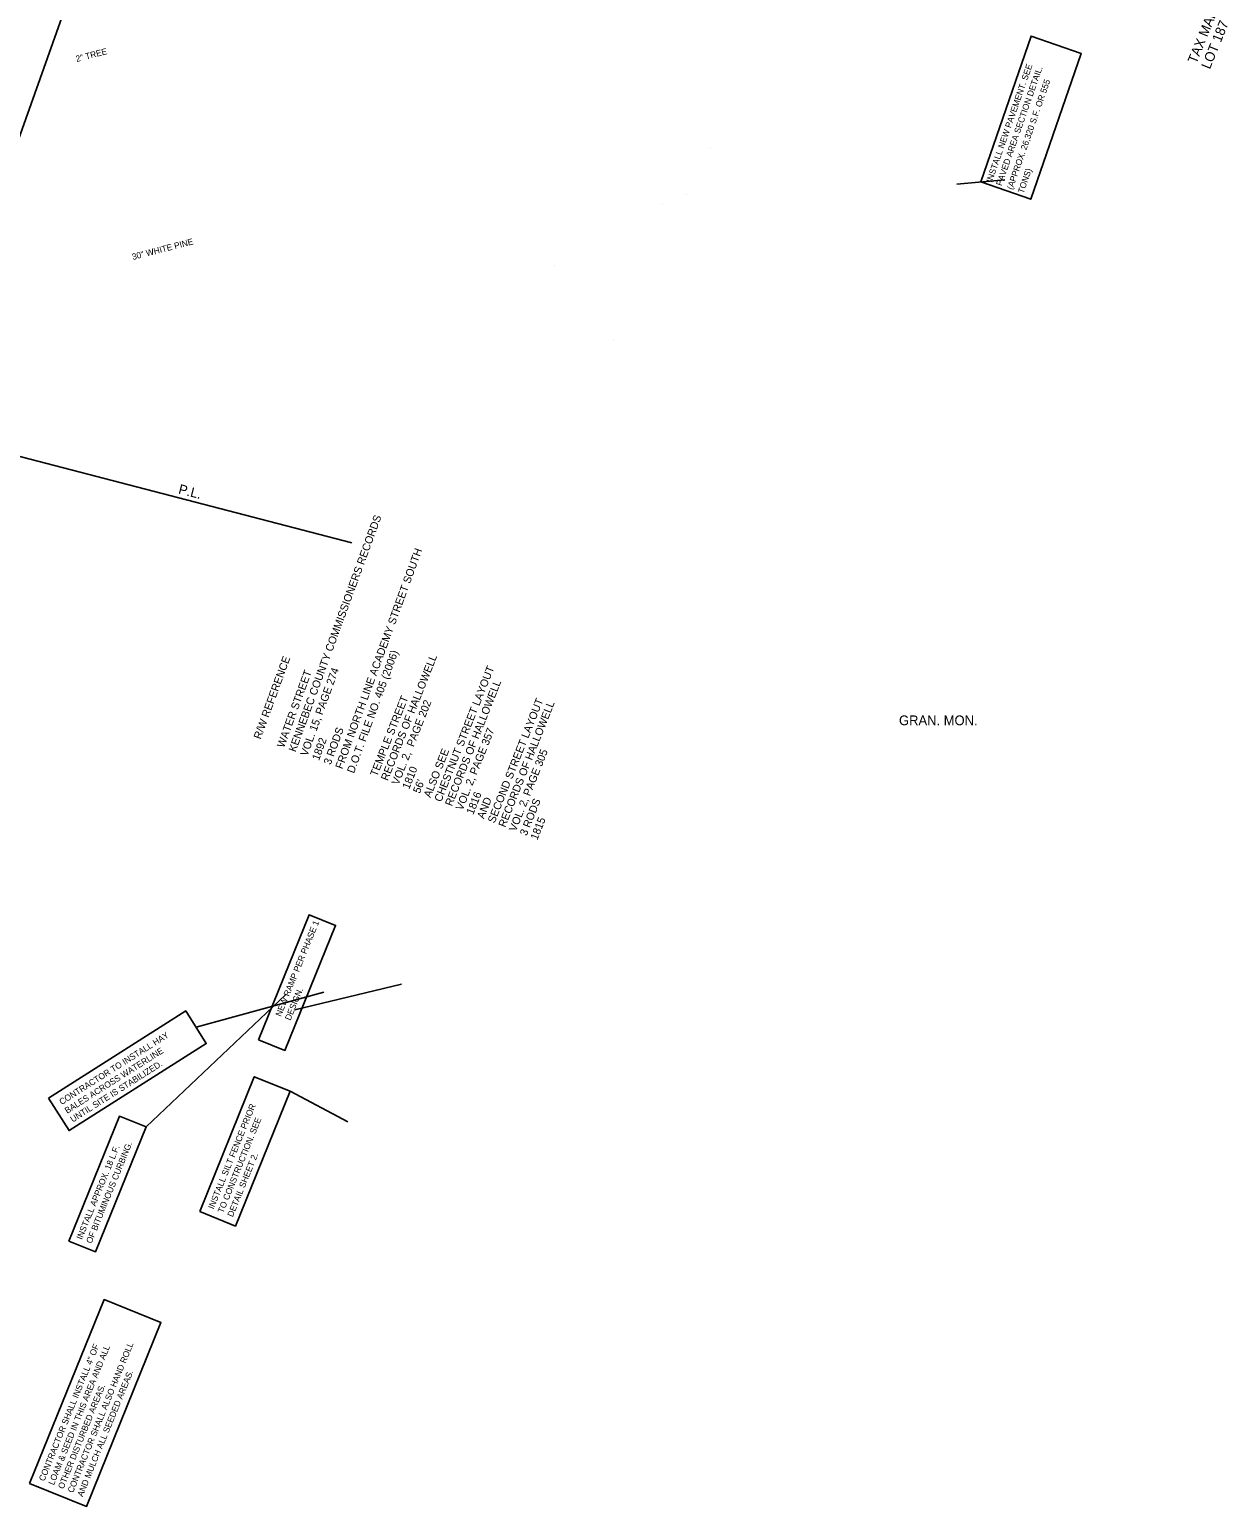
# Model space of a CAD drawing. Extents: x 1133267 to 1139526, y 528613 to 531538.
# Drawn here: x 1137149.8 to 1137458.4, y 528613.1 to 528993.4 of the extents above; entities that cross this region are included whole.
import ezdxf

# ---------------------------------------------------------------- set-up
doc = ezdxf.new("R2010")
doc.units = 0
for name, color, linetype in [('E_Property_Line', 7, 'Continuous'), ('E_ROW_Line', 7, 'Continuous'), ('MISCELLN TEXT', 7, 'Continuous'), ('P_Ease_Temp_Grading_Line', 7, 'Continuous'), ('P_ROW_Tie_Lines', 7, 'Continuous'), ('PROPERTY LINES', 7, 'Continuous'), ('PROPERTY NOTES', 7, 'Continuous'), ('ROW REFERENCES', 7, 'Continuous'), ('TEXT', 7, 'Continuous'), ('TEXT-PHASE-2', 7, 'Continuous')]:
    doc.layers.add(name, color=color, linetype=linetype)

msp = doc.modelspace()

# ---------------------------------------------------------------- linework, layer by layer
at = {"layer": 'E_Property_Line'}
msp.add_line((1137122, 528890.03), (1137232.78, 528861.28), dxfattribs=at)
at = {"layer": 'E_ROW_Line'}
msp.add_line((1137334.82, 529494.05), (1137099.12, 528830.58), dxfattribs=at)
at = {"layer": 'P_Ease_Temp_Grading_Line'}
for p, q in [((1137325.21, 528963.14), (1137325.21, 528963.14)), ((1137312.9, 528948.25), (1137312.9, 528948.25)), ((1137319.01, 528950.82), (1137319.01, 528950.82)), ((1137284.91, 528932.58), (1137284.91, 528932.58)), ((1137300.12, 528913.5), (1137300.12, 528913.5))]:
    msp.add_line(p, q, dxfattribs=at)
at = {"layer": 'P_ROW_Tie_Lines'}
for p, q in [((1137400.99, 528954.7), (1137388.64, 528953.61)), ((1137218.15, 528741), (1137245.61, 528747.58)), ((1137179.79, 528710.86), (1137215.75, 528744.89)), ((1137192.66, 528736.52), (1137225.59, 528745.57)), ((1137216.88, 528720.06), (1137231.76, 528712.18))]:
    msp.add_line(p, q, dxfattribs=at)
at = {"layer": 'TEXT'}
msp.add_lwpolyline([(1137154.65, 528718.3), (1137190, 528740.71), (1137195.31, 528732.33), (1137159.96, 528709.91)], close=True, dxfattribs=at)
at = {"layer": 'TEXT-PHASE-2'}
for points in [[(1137394.81, 528954.16), (1137407.79, 528991.7), (1137420.65, 528987.26), (1137407.67, 528949.71)], [(1137208.74, 528733.31), (1137221.78, 528765.5), (1137228.62, 528762.72), (1137215.58, 528730.54)], [(1137193.61, 528689.05), (1137207.68, 528723.79), (1137216.88, 528720.06), (1137202.81, 528685.32)], [(1137159.91, 528681.45), (1137172.94, 528713.63), (1137179.79, 528710.86), (1137166.75, 528678.67)], [(1137149.8, 528619.09), (1137168.97, 528666.42), (1137183.64, 528660.48), (1137164.47, 528613.15)]]:
    msp.add_lwpolyline(points, close=True, dxfattribs=at)

# ---------------------------------------------------------------- texts
at = {"layer": 'MISCELLN TEXT'}
msp.add_text('GRAN. MON.', height=2.5, dxfattribs=at).set_placement((1137373.75, 528814.29))
at = {"layer": 'PROPERTY LINES'}
msp.add_text('P.L.', height=2.49, rotation=345.7573, dxfattribs=at).set_placement((1137187.97, 528873.96))
at = {"layer": 'PROPERTY NOTES'}
for s, p in [('TAX MAP 9', (1137450.34, 528984.43)), ('LOT 187', (1137453.82, 528983.02))]:
    msp.add_text(s, height=2.5, rotation=67.8489, dxfattribs=at).set_placement(p)
at = {"layer": 'ROW REFERENCES'}
for s, rotation, p in [('KENNEBEC COUNTY COMMISSIONERS RECORDS', 69.9596, (1137218.32, 528807.24)), ('FROM NORTH LINE ACADEMY STREET SOUTH', 69.9596, (1137230.35, 528802.86)), ('R/W REFERENCE', 69.9596, (1137209.3, 528810.53)), ('D.O.T. FILE NO. 405 (2006)', 69.9596, (1137233.35, 528801.76)), ('RECORDS OF HALLOWELL', 68.3945, (1137242.06, 528799.83)), ('WATER STREET', 69.9596, (1137215.32, 528808.34)), ('VOL. 15, PAGE 274', 69.9596, (1137221.33, 528806.15)), ('CHESTNUT STREET LAYOUT', 68.3945, (1137255.82, 528794.38)), ('RECORDS OF HALLOWELL', 68.3945, (1137258.57, 528793.29)), ('TEMPLE STREET', 68.3945, (1137239.3, 528800.92)), ('VOL. 2,  PAGE 202', 68.3945, (1137244.81, 528798.74)), ('SECOND STREET LAYOUT', 68.3945, (1137269.58, 528788.93)), ('RECORDS OF HALLOWELL', 68.3945, (1137272.33, 528787.84)), ('3 RODS', 69.9596, (1137227.34, 528803.95)), ('VOL. 2, PAGE 357', 68.3945, (1137261.32, 528792.2)), ('1892', 69.9596, (1137224.33, 528805.05)), ('ALSO SEE', 68.3945, (1137253.06, 528795.47)), ('VOL. 2, PAGE 305', 68.3945, (1137275.08, 528786.75)), ('1810', 68.3945, (1137247.56, 528797.65)), ("56'", 68.3945, (1137250.31, 528796.56)), ('1816', 68.3945, (1137264.07, 528791.11)), ('AND', 68.3945, (1137266.82, 528790.02)), ('3 RODS', 68.3945, (1137277.83, 528785.66)), ('1815', 68.3945, (1137280.58, 528784.57))]:
    msp.add_text(s, height=2, rotation=rotation, dxfattribs=at).set_placement(p)
at = {"layer": 'TEXT'}
for s, height, rotation, p in [('2" TREE', 1.599, 14.4857, (1137161.91, 528985.02)), ('30" WHITE PINE', 1.5987, 14.4857, (1137176.4, 528934.05)), ('CONTRACTOR TO INSTALL HAY ', 1.5987, 32.381, (1137158.06, 528716.47)), ('BALES ACROSS WATERLINE ', 1.5987, 32.381, (1137159.48, 528714.22)), ('UNTIL SITE IS STABILIZED.', 1.5987, 32.381, (1137160.91, 528711.97))]:
    msp.add_text(s, height=height, rotation=rotation, dxfattribs=at).set_placement(p)
at = {"layer": 'TEXT-PHASE-2'}
for s, height, rotation, p in [('INSTALL NEW PAVEMENT. SEE ', 1.5987, 70.9384, (1137397.68, 528953.88)), ('PAVED AREA SECTION DETAIL.  ', 1.5987, 70.9384, (1137400.2, 528953.01)), ('(APPROX. 26,320 S.F. OR 555 ', 1.5987, 70.9384, (1137403.01, 528952.03)), ('TONS)', 1.599, 70.9384, (1137405.81, 528951.06)), ('NEW RAMP PER PHASE 1 ', 1.5987, 67.9509, (1137214.53, 528739.15)), ('DESIGN.', 1.599, 67.9509, (1137216.99, 528738.15)), ('INSTALL SILT FENCE PRIOR ', 1.5987, 67.9509, (1137197.2, 528689.55)), ('TO CONSTRUCTION. SEE ', 1.5987, 67.9509, (1137199.67, 528688.54)), ('INSTALL APPROX. 18 L.F. ', 1.5987, 67.9509, (1137163.29, 528681.71)), ('OF BITUMINOUS CURBING.', 1.5987, 67.9509, (1137165.76, 528680.71)), ('DETAIL SHEET 2.', 1.5987, 67.9509, (1137202.14, 528687.54)), ('CONTRACTOR SHALL INSTALL 4" OF ', 1.5987, 67.9509, (1137153.58, 528619.51)), ('LOAM & SEED IN THIS AREA AND ALL ', 1.5987, 67.9509, (1137156.05, 528618.51)), ('CONTRACTOR SHALL ALSO HAND ROLL ', 1.5987, 67.9509, (1137160.99, 528616.51)), ('AND MULCH ALL SEEDED AREAS.', 1.5987, 67.9509, (1137163.46, 528615.51)), ('OTHER DISTURBED AREAS. ', 1.5987, 67.9509, (1137158.52, 528617.51))]:
    msp.add_text(s, height=height, rotation=rotation, dxfattribs=at).set_placement(p)

doc.saveas('drawing.dxf')
